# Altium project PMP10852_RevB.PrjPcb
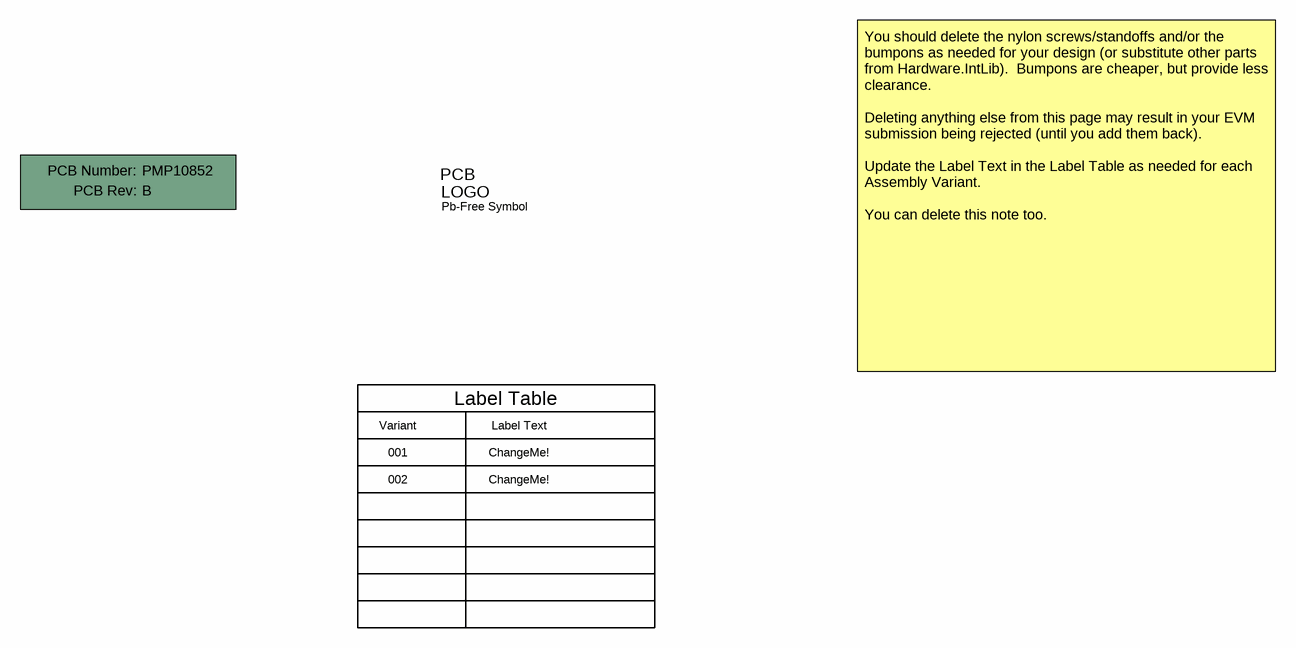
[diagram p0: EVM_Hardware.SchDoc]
CopyrightYear: 2014; PCB_Layout: Who did the Layout?; PCB_Rev: B; PRJ_Customer: Public Release; PRJ_Engineer: Enter name of project lead; PRJ_Number: PMP10852; PRJ_Title: Change in menu Project|Project Options|Parameters; SCH_Rev: B; TechSupport: http://www.ti.com/support; TID: N/A
2 sheets, 51 parts. Net scope: global (net labels, ports and power ports of the same name join across sheets).
Board file: EVM_RevB.PcbDoc
Sheets:
  EVM_Hardware.SchDoc
  BlankSheet_RevB.SchDoc

## Sheet EVM_Hardware.SchDoc
size 431 x 279 mm; Date: Not shown in title block; ApprovedBy: Not shown in title block; CheckedBy: Not shown in title block; Author: Not shown in title block; CompanyName: Not shown in title block; Engineer: Not shown in title block; Organization: Not shown in title block; Address1: Not shown in title block; Address2: Not shown in title block; Address3: Not shown in title block; Address4: Not shown in title block; DocumentNumber: 1; Revision: Use project parameter SCH_Rev; SheetNumber: 3; SheetTotal: 3; PageSetup: Record=PageOptions¦CenterHorizontal=True¦CenterVertical=True¦PrintScale=1.00¦XCorrection=1.00¦YCorrection=1.00¦PrintKind=0¦BorderSize=5000000¦LeftOffset=0¦BottomOffset=0¦Orientation=2¦PaperLength=1000¦PaperWidth=1000¦Scale=100¦PaperSource=15¦PrintQuality=600¦MediaType=1¦DitherType=10¦PaperKind=Letter¦PrintScaleMode=1

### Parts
!PCB  Printed Circuit Board  (value not drawn)  (mechanical)
Logo2  Pb-Free Symbol  [Pb-Free_Overlay_Small]  (no BOM)

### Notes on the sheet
- Variant
- Label Table
- Label Text
- You should delete the nylon screws/standoffs and/or the bumpons as needed for your design (or substitute other parts from Hardware.IntLib).  Bumpons are cheaper, but provide less clearance.
  Deleting anything else from this page may result in your EVM submission being rejected (until you add them back).
  Update the Label Text in the Label Table as needed for each Assembly Variant.
  You can delete this note too.
- 001
- 002
- ChangeMe!

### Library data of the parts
!PCB = PCB: Manufacturer: Any; PartNumber: PMP10852; SymbolCreator: a0412235
Logo2 = Pb-Free: SymbolCreator: a0412235

## Sheet BlankSheet_RevB.SchDoc
size 431 x 279 mm; Date: Not shown in title block; ApprovedBy: Not shown in title block; CheckedBy: Not shown in title block; Author: Not shown in title block; CompanyName: Not shown in title block; Engineer: Not shown in title block; Organization: Not shown in title block; Address1: Not shown in title block; Address2: Not shown in title block; Address3: Not shown in title block; Address4: Not shown in title block; DocumentNumber: 1; Revision: Use project parameter SCH_Rev; SheetNumber: 2; SheetTotal: 3; PageSetup: Record=PageOptions¦CenterHorizontal=True¦CenterVertical=True¦PrintScale=1.00¦XCorrection=1.00¦YCorrection=1.00¦PrintKind=0¦BorderSize=5000000¦LeftOffset=0¦BottomOffset=0¦Orientation=2¦PaperLength=1000¦PaperWidth=1000¦Scale=100¦PaperSource=15¦PrintQuality=600¦MediaType=1¦DitherType=10¦PaperKind=Letter¦PrintScaleMode=1
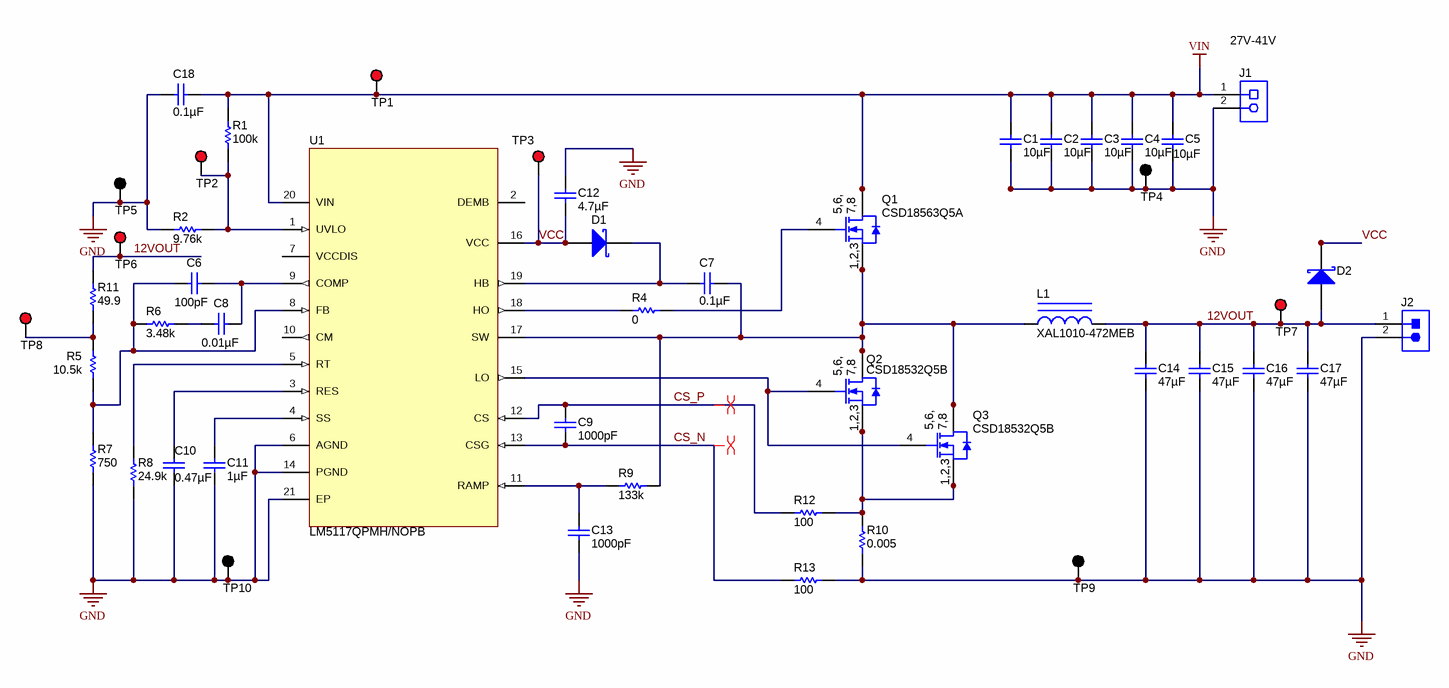
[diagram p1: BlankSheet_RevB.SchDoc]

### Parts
C1  ValueDisplayed: 10µF  [1210]  (hidden comment: GRM32ER71H106KA12L)
C2  ValueDisplayed: 10µF  [1210]  (hidden comment: GRM32ER71H106KA12L)
C3  ValueDisplayed: 10µF  [1210]  (hidden comment: GRM32ER71H106KA12L)
C4  ValueDisplayed: 10µF  [1210]  (hidden comment: GRM32ER71H106KA12L)
C5  ValueDisplayed: 10µF  [1210]  (hidden comment: GRM32ER71H106KA12L)
C6  ValueDisplayed: 100pF  [0402S]  (hidden comment: CC0402JRNPO9BN101)
C7  ValueDisplayed: 0.1µF  [0402S]  (hidden comment: C1005X7R1H104K050BB)
C8  ValueDisplayed: 0.01µF  [0402]  (hidden comment: GRM155R61C103KA01D)
C9  ValueDisplayed: 1000pF  [0402S]  (hidden comment: GRM155R72A102KA01D)
C10  ValueDisplayed: 0.47µF  [0402S]  (hidden comment: GRM155C80G474KE01D)
C11  ValueDisplayed: 1µF  [0402S]  (hidden comment: C1005X5R1C105K050BC)
C12  ValueDisplayed: 4.7µF  [0402S]  (hidden comment: GRM155R61E475ME15)
C13  ValueDisplayed: 1000pF  [0402S]  (hidden comment: GRM155R72A102KA01D)
C14  ValueDisplayed: 47µF  [1206]  (hidden comment: C3216X5R1E476M160AC)
C15  ValueDisplayed: 47µF  [1206]  (hidden comment: C3216X5R1E476M160AC)
C16  ValueDisplayed: 47µF  [1206]  (hidden comment: C3216X5R1E476M160AC)
C17  ValueDisplayed: 47µF  [1206]  (hidden comment: C3216X5R1E476M160AC)
C18  ValueDisplayed: 0.1µF  [0402S]  (hidden comment: C1005X7R1H104K050BB)
D1  1N5819HW-7-F  [SOD-123]  (value not drawn)
D2  1N5819HW-7-F  [SOD-123]  (value not drawn)
J1  OSTTC022162  [On-Shore_OSTTC022162]  (value not drawn)
J2  OSTT7022150  [TERM_BLK_OSTT7022150]  (value not drawn)
L1  XAL1010-472MEB  [XAL1010]
Q1  CSD18563Q5A  [TRANS_NexFET_Q5A]
Q2  CSD18532Q5B  [TRANS_NexFET_Q5B]
Q3  CSD18532Q5B  [TRANS_NexFET_Q5B]
R1  ValueDisplayed: 100k  [0402S]  (hidden comment: CRCW0402100KFKED)
R2  ValueDisplayed: 9.76k  [0402S]  (hidden comment: CRCW04029K76FKED)
R4  ValueDisplayed: 0  [0402S]  (hidden comment: CRCW04020000Z0ED)
R5  ValueDisplayed: 10.5k  [0402S]  (hidden comment: CRCW040210K5FKED)
R6  ValueDisplayed: 3.48k  [0402S]  (hidden comment: CRCW04023K48FKED)
R7  ValueDisplayed: 750  [0402S]  (hidden comment: CRCW0402750RFKED)
R8  ValueDisplayed: 24.9k  [0402]  (hidden comment: CRCW040224K9FKED)
R9  ValueDisplayed: 133k  [0402]  (hidden comment: CRCW0402133KFKED)
R10  ValueDisplayed: 0.005  [1210M]  (hidden comment: PMR25HZPFU5L00)
R11  ValueDisplayed: 49.9  [0402S]  (hidden comment: CRCW040249R9FKED)
R12  ValueDisplayed: 100  [0402]  (hidden comment: CRCW0402100RFKED)
R13  ValueDisplayed: 100  [0402]  (hidden comment: CRCW0402100RFKED)
TP1  5000  [Keystone5000]  (value not drawn)
TP2  5000  [Keystone5000]  (value not drawn)
TP3  5000  [Keystone5000]  (value not drawn)
TP4  5011  [Keystone5011]  (value not drawn)
TP5  5011  [Keystone5011]  (value not drawn)
TP6  5000  [Keystone5000]  (value not drawn)
TP7  5000  [Keystone5000]  (value not drawn)
TP8  5000  [Keystone5000]  (value not drawn)
TP9  5011  [Keystone5011]  (value not drawn)
TP10  5011  [Keystone5011]  (value not drawn)
U1  LM5117QPMH/NOPB  [PWP0020A_L]

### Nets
GND: C1.2 C2.2 C3.2 C4.2 C5.2 C10.2 C11.2 C12.1 C13.2 C14.2 C15.2 C16.2 C17.2 C18.2 J1.2 J2.2 R2.2 R7.1 R8.1 R10.1 R13.2 TP4.1 TP5.1 TP9.1 TP10.1 U1.6(AGND) U1.14(PGND) U1.21(EP)
VIN: C1.1 C2.1 C3.1 C4.1 C5.1 C18.1 J1.1 Q1.5(D) Q1.6(D) Q1.7(D) Q1.8(D) Q1.9(D) R1.2 TP1.1 U1.20(VIN)
12VOUT: C14.1 C15.1 C16.1 C17.1 D2.2(A) J2.1 L1.2 R11.2 TP6.1 TP7.1
CS_N: C9.2 R13.1 U1.13(CSG)
CS_P: C9.1 R12.1 U1.12(CS)
VCC: C12.2 D1.2(A) D2.1(K) TP3.1 U1.16(VCC)
NetC6_1: C6.1 C8.1 U1.9(COMP)
NetC6_2: C6.2 R5.2 R6.1 R7.2 U1.8(FB)
NetC7_1: C7.1 L1.1 Q1.1(S) Q1.2(S) Q1.3(S) Q2.5(D) Q2.6(D) Q2.7(D) Q2.8(D) Q3.5(D) Q3.6(D) Q3.7(D) Q3.8(D) R9.2 U1.17(SW)
NetC7_2: C7.2 D1.1(K) U1.19(HB)
NetC8_2: C8.2 R6.2
NetC10_1: C10.1 U1.3(RES)
NetC11_1: C11.1 U1.4(SS)
NetC13_1: C13.1 R9.1 U1.11(RAMP)
NetQ1_4: Q1.4(G) R4.2
NetQ2_1: Q2.1(S) Q2.2(S) Q2.3(S) Q3.1(S) Q3.2(S) Q3.3(S) R10.2 R12.2
NetQ2_4: Q2.4(G) Q3.4(G) U1.15(LO)
NetR1_1: R1.1 R2.1 TP2.1 U1.1(UVLO)
NetR4_1: R4.1 U1.18(HO)
NetR5_1: R5.1 R11.1 TP8.1
NetR8_2: R8.2 U1.5(RT)

Not connected (* = marked no-connect by the designer): U1 2(DEMB) 7(VCCDIS) 10(CM)

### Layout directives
differential pair: CS_N, CS_P

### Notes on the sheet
- (near J1) 27V-41V

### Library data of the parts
C1-C5 = GRM32ER71H106KA12L: CAP, CERM, 10 µF, 50 V, +/- 10%, X7R, 1210; Manufacturer: MuRata; Polarized: N; CompType: Capacitor; Value: 10uF; U/M: EA; Cap_F: 0.00001; Tolerance_%: 10; Value1: Unknown; VDC_V: 50; Value2: 50V; TaMin_C: -55; TaMax_C: 125
C6 = CC0402JRNPO9BN101: CAP, CERM, 100 pF, 50 V, +/- 5%, C0G/NP0, 0402; Manufacturer: Yageo America; Polarized: N; CompType: Capacitor; Value: 100pF; U/M: EA; Cap_F: 0.0000000001; Tolerance_%: 5; Value1: Unknown; VDC_V: 50; Value2: 50V; TaMin_C: -55; TaMax_C: 125; Cap_Case: 0402
C7 C18 = C1005X7R1H104K050BB: CAP, CERM, 0.1 µF, 50 V, +/- 10%, X7R, 0402; Manufacturer: TDK; Polarized: N; CompType: Capacitor; Value: 0.1uF; U/M: EA; Cap_F: 0.0000001; Tolerance_%: 10; Value1: Unknown; VDC_V: 50; Value2: 50V; TaMin_C: -55; TaMax_C: 125; Cap_Case: 0402
C8 = GRM155R61C103KA01D: CAP, CERM, 0.01 µF, 16 V, +/- 10%, X5R, 0402; Manufacturer: MuRata; Polarized: N; CompType: Capacitor; Value: 0.01uF; U/M: EA; Cap_F: 0.00000001; Tolerance_%: 10; Value1: Unknown; VDC_V: 16; Value2: 16V; TaMin_C: -55; TaMax_C: 85
C9 C13 = GRM155R72A102KA01D: CAP, CERM, 1000 pF, 100 V, +/- 10%, X7R, 0402; Manufacturer: MuRata; Polarized: N; CompType: Capacitor; Value: 1000pF; U/M: EA; Cap_F: 0.000000001; Tolerance_%: 10; Value1: Unknown; VDC_V: 100; Value2: 100V; TaMin_C: -55; TaMax_C: 125; Cap_Case: 0402
C10 = GRM155C80G474KE01D: CAP, CERM, 0.47 µF, 4 V, +/- 10%, X6S, 0402; Manufacturer: MuRata; Polarized: N; CompType: Capacitor; Value: 0.47uF; U/M: EA; Cap_F: 0.00000047; Tolerance_%: 10; Value1: Unknown; VDC_V: 4; Value2: 4V; TaMin_C: -55; TaMax_C: 105; Cap_Case: 0402
C11 = C1005X5R1C105K050BC: CAP, CERM, 1 µF, 16 V, +/- 10%, X5R, 0402; Manufacturer: TDK; Polarized: N; CompType: Capacitor; Value: 1uF; U/M: EA; Cap_F: 0.000001; Tolerance_%: 10; Value1: Unknown; VDC_V: 16; Value2: 16V; TaMin_C: -55; TaMax_C: 85; Cap_Case: 0402
C12 = GRM155R61E475ME15: CAP, CERM, 4.7 µF, 25 V, +/- 20%, X5R, 0402; Manufacturer: MuRata; Polarized: N; CompType: Capacitor; Value: 4.7uF; U/M: EA; Cap_F: 0.0000047; Tolerance_%: 20; Value1: Unknown; VDC_V: 25; Value2: 25V; TaMin_C: -55; TaMax_C: 85; Cap_Case: 0402
C14-C17 = C3216X5R1E476M160AC: CAP, CERM, 47 µF, 25 V, +/- 20%, X5R, 1206; Manufacturer: TDK; Polarized: N; CompType: Capacitor; Value: 47uF; U/M: EA; Cap_F: 0.000047; Tolerance_%: 20; Value1: Unknown; VDC_V: 25; Value2: 25V; TaMin_C: -55; TaMax_C: 85
D1 D2 = 1N5819HW-7-F: Diode, Schottky, 40 V, 1 A, SOD-123; Manufacturer: Diodes Inc.; U/M: EA; Vf_V: 0.45; Value: 40V; Value1: 1A; Value2: 0.45V; Io_A: 1; Vr_V: 40; TJmax_C: 125
J1 = OSTTC022162: Terminal Block, 2-pole, 200mil, TH; Manufacturer: On-Shore Technology; SymbolCreator: a0412235; U/M: EA
J2 = OSTT7022150: Terminal Block, 30A, 9.52mm (.375) Pitch, 2-Pos, TH; Manufacturer: On-Shore Technology; SymbolCreator: a0412235; CompType: Connector; U/M: EA
L1 = XAL1010-472MEB: Inductor, Shielded, Composite, 4.7 µH, 24 A, 0.01 ohm, SMD; Manufacturer: Coilcraft; Value: 4.7uH; Ind_H: 4.7E-6; ValueDisplayed: 4.7µH; Imax_A: 24; Irms: 24A @ 40C rise; Isat: 25.4A @ 30% inductance drop; DCR_ohm: 0.01; Value2: 24A
Q1 = CSD18563Q5A: MOSFET, N-CH, 60 V, 15 A, SON 5x6mm; Manufacturer: Texas Instruments; Alternate Manufacturer: None; U/M: EA; ChType: N; Value: 60V; VdsMax_V: 60; Value1: 0.0086 ohm; Rdson45_ohm: 0.0086; Value2: 15 nC; QgTyp_nC: 15; Vgs_V: 20
Q2 Q3 = CSD18532Q5B: MOSFET, N-CH, 60 V, 172 A, SON 5x6mm; Manufacturer: Texas Instruments; Alternate Manufacturer: None; U/M: EA; ChType: N; Value: 60V; VdsMax_V: 60; Value1: 3.3 ohm; Rdson45_ohm: 3.3; Value2: 27 nC; QgTyp_nC: 27; Vgs_V: 1.6; IdsMax_A: 172
R1 = CRCW0402100KFKED: RES, 100 k, 1%, 0.063 W, 0402; Manufacturer: Vishay-Dale; CompType: Resistor; Value: 100k; Res_ohm: 100000; Tolerance_%: 1; Power_W: 0.063; Value2: 0.063W; VDC_V: 50; TempCo: 100 ppm/C; EIA_Code: E96; U/M: EA
R2 = CRCW04029K76FKED: RES, 9.76 k, 1%, 0.063 W, 0402; Manufacturer: Vishay-Dale; CompType: Resistor; Value: 9.76k; Res_ohm: 9760; Value_Code: 9k76; Tolerance_%: 1; Power_W: 0.063; Value2: 0.063W; VDC_V: 50; TempCo: 100 ppm/C; EIA_Code: E96; U/M: EA
R4 = CRCW04020000Z0ED: RES, 0, 5%, 0.063 W, 0402; Manufacturer: Vishay-Dale; CompType: Resistor; Value: 0; Value_Code: 0000; Tolerance_%: 5; Power_W: 0.063; Value2: 0.063W; VDC_V: 50; TempCo: 200 ppm/C; EIA_Code: E24; U/M: EA
R5 = CRCW040210K5FKED: RES, 10.5 k, 1%, 0.063 W, 0402; Manufacturer: Vishay-Dale; CompType: Resistor; Value: 10.5k; Res_ohm: 10500; Value_Code: 10k5; Tolerance_%: 1; Power_W: 0.063; Value2: 0.063W; VDC_V: 50; TempCo: 100 ppm/C; EIA_Code: E96; U/M: EA
R6 = CRCW04023K48FKED: RES, 3.48 k, 1%, 0.063 W, 0402; Manufacturer: Vishay-Dale; CompType: Resistor; Value: 3.48k; Res_ohm: 3480; Value_Code: 3k48; Tolerance_%: 1; Power_W: 0.063; Value2: 0.063W; VDC_V: 50; TempCo: 100 ppm/C; EIA_Code: E96; U/M: EA
R7 = CRCW0402750RFKED: RES, 750, 1%, 0.063 W, 0402; Manufacturer: Vishay-Dale; CompType: Resistor; Value: 750; Value_Code: 750R; Tolerance_%: 1; Power_W: 0.063; Value2: 0.063W; VDC_V: 50; TempCo: 100 ppm/C; EIA_Code: E96; U/M: EA
R8 = CRCW040224K9FKED: RES, 24.9 k, 1%, 0.063 W, 0402; Manufacturer: Vishay-Dale; CompType: Resistor; Value: 24.9k; Res_ohm: 24900; Value_Code: 24k9; Tolerance_%: 1; Power_W: 0.063; Value2: 0.063W; VDC_V: 50; TempCo: 100 ppm/C; EIA_Code: E96; U/M: EA
R9 = CRCW0402133KFKED: RES, 133 k, 1%, 0.063 W, 0402; Manufacturer: Vishay-Dale; CompType: Resistor; Value: 133k; Res_ohm: 133000; Tolerance_%: 1; Power_W: 0.063; Value2: 0.063W; VDC_V: 50; TempCo: 100 ppm/C; EIA_Code: E96; U/M: EA
R10 = PMR25HZPFU5L00: RES, 0.005, 1%, 1 W, 1210; Manufacturer: Rohm; CompType: Resistor; Value: 0.005; Value_Code: 5L000; Tolerance_%: 1; Value2: 1W; TempCo: 100 ppm/C; EIA_Code: E96; U/M: EA
R11 = CRCW040249R9FKED: RES, 49.9, 1%, 0.063 W, 0402; Manufacturer: Vishay-Dale; CompType: Resistor; Value: 49.9; Value_Code: 49R9; Tolerance_%: 1; Power_W: 0.063; Value2: 0.063W; VDC_V: 50; TempCo: 100 ppm/C; EIA_Code: E96; U/M: EA
R12 R13 = CRCW0402100RFKED: RES, 100, 1%, 0.063 W, 0402; Manufacturer: Vishay-Dale; CompType: Resistor; Value: 100; Value_Code: 100R; Tolerance_%: 1; Power_W: 0.063; Value2: 0.063W; VDC_V: 50; TempCo: 100 ppm/C; EIA_Code: E96; U/M: EA
TP1-TP3 TP6-TP8 = 5000: Test Point, Miniature, Red, TH; Manufacturer: Keystone; CompType: Test Point Loop; U/M: EA
TP4 TP5 TP9 TP10 = 5011: Test Point, Multipurpose, Black, TH; Manufacturer: Keystone; CompType: Test Point Loop; U/M: EA
U1 = LM5117QPMH/NOPB: Wide Input Range Synchronous Buck Controller with Analog Current Monitor, PWP0020A; Manufacturer: Texas Instruments; SymbolCreator: a0411947; CompType: IC; U/M: EA

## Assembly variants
001: all parts fitted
